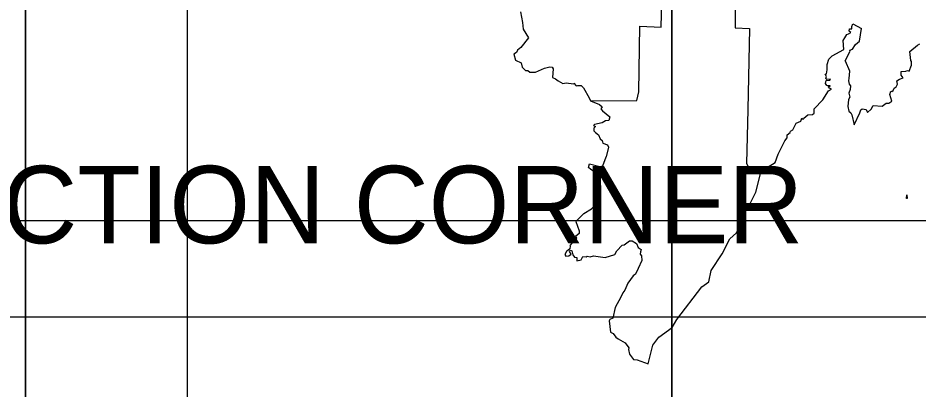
# Model space of a CAD drawing. Extents: x 2146475 to 2147951, y 2147003 to 2148003.
# Drawn here: x 2147652.9 to 2147708.6, y 2147812.5 to 2147835.5 of the extents above; entities that cross this region are included whole.
import ezdxf

# ---------------------------------------------------------------- set-up
doc = ezdxf.new("R2010")
doc.units = 0
for name, color, linetype in [('Sheet_Border_Prof3_Grid+Sta+EL_04_040+08_080', 7, 'Continuous'), ('Sheet_Border_Prof3_Grid+Sta+EL_10_100+20_200', 7, 'Continuous'), ('Sheet_Border_TitleSheet', 7, 'Continuous'), ('Sheet_Border_XS_Grid', 7, 'Continuous'), ('Sheet_Label_Misc_Wt1', 7, 'Continuous')]:
    doc.layers.add(name, color=color, linetype=linetype)

msp = doc.modelspace()

# ---------------------------------------------------------------- linework, layer by layer
at = {"layer": 'Sheet_Border_Prof3_Grid+Sta+EL_04_040+08_080'}
msp.add_line((2147663.414, 2147910.951), (2147663.414, 2147136.951), dxfattribs=at)
at = {"layer": 'Sheet_Border_Prof3_Grid+Sta+EL_10_100+20_200'}
for p, q in [((2147653.414, 2147896.951), (2147653.414, 2147152.951)), ((2147693.414, 2147896.951), (2147693.414, 2147152.951)), ((2147813.414, 2147816.951), (2146613.414, 2147816.951))]:
    msp.add_line(p, q, dxfattribs=at)
at = {"layer": 'Sheet_Border_TitleSheet'}
for points in [[(2147691.379, 2147830.925), (2147691.437, 2147834.989), (2147692.762, 2147834.927), (2147692.813, 2147837.395)], [(2147697.355, 2147837.179), (2147697.33, 2147834.879), (2147698.213, 2147834.845), (2147698.11, 2147829.821)], [(2147684.047, 2147835.863), (2147684.162, 2147835.217), (2147684.22, 2147834.797), (2147684.55, 2147834.253)], [(2147704.054, 2147833.539), (2147704.026, 2147834.097), (2147704.12, 2147834.269), (2147704.249, 2147834.465), (2147704.355, 2147834.513), (2147704.489, 2147834.597), (2147704.382, 2147834.667), (2147704.419, 2147834.823), (2147704.56, 2147834.811), (2147704.547, 2147834.955), (2147704.62, 2147835.121), (2147705.162, 2147834.839)], [(2147704.142, 2147832.835), (2147704.457, 2147833.431), (2147704.434, 2147833.495), (2147704.585, 2147833.565), (2147704.782, 2147833.849), (2147705.02, 2147834.053), (2147705.162, 2147834.839)], [(2147684.55, 2147834.253), (2147684.069, 2147833.663), (2147683.861, 2147833.497), (2147683.809, 2147833.351), (2147683.64, 2147833.241), (2147683.729, 2147832.887), (2147684.096, 2147832.721), (2147684.158, 2147832.435), (2147684.365, 2147832.239), (2147684.495, 2147832.247), (2147684.618, 2147832.143), (2147684.978, 2147832.125), (2147685.54, 2147832.381)], [(2147708.134, 2147833.425), (2147708.609, 2147833.817), (2147708.762, 2147833.881)], [(2147702.766, 2147830.419), (2147703.11, 2147830.981), (2147703.3, 2147831.085), (2147703.164, 2147831.145), (2147703.093, 2147831.259), (2147703.221, 2147831.261), (2147703.209, 2147831.291), (2147703.003, 2147831.319), (2147702.93, 2147831.429), (2147702.972, 2147831.621), (2147703.192, 2147831.645), (2147703.227, 2147831.705), (2147703.016, 2147831.679), (2147702.951, 2147831.751), (2147702.99, 2147831.859), (2147702.911, 2147832.009), (2147702.986, 2147832.041), (2147703.033, 2147832.281), (2147703.02, 2147832.617), (2147703.132, 2147832.935), (2147703.34, 2147833.155), (2147704.054, 2147833.539)], [(2147704.693, 2147828.883), (2147705.041, 2147829.621), (2147705.103, 2147829.811), (2147705.191, 2147829.863), (2147705.443, 2147829.813), (2147705.53, 2147829.647), (2147705.742, 2147829.835), (2147705.88, 2147830.079), (2147706.439, 2147830.019), (2147706.679, 2147830.205), (2147706.85, 2147830.211), (2147707.022, 2147830.347), (2147706.899, 2147830.749), (2147706.966, 2147830.959), (2147707.023, 2147830.937), (2147707.107, 2147830.995), (2147707.177, 2147831.135), (2147707.303, 2147831.219), (2147707.382, 2147831.399), (2147707.333, 2147831.603), (2147707.505, 2147831.703), (2147707.731, 2147831.779), (2147707.61, 2147831.943), (2147707.608, 2147832.173), (2147707.898, 2147832.195), (2147708.005, 2147832.247), (2147708.097, 2147832.203), (2147708.247, 2147832.577), (2147708.252, 2147832.795), (2147708.2, 2147832.855), (2147708.134, 2147833.425)], [(2147704.142, 2147832.835), (2147704.412, 2147832.215), (2147704.393, 2147831.941), (2147704.364, 2147831.765), (2147704.356, 2147831.595), (2147704.393, 2147831.399), (2147704.461, 2147831.283), (2147704.452, 2147831.061), (2147704.376, 2147830.825), (2147704.429, 2147830.585), (2147704.35, 2147830.439), (2147704.299, 2147830.015), (2147704.363, 2147829.709), (2147704.498, 2147829.615), (2147704.561, 2147829.487), (2147704.693, 2147828.883)], [(2147685.54, 2147832.381), (2147685.865, 2147832.469), (2147686.001, 2147832.453), (2147686.06, 2147832.343)], [(2147686.06, 2147832.343), (2147686.033, 2147831.799), (2147686.222, 2147831.713), (2147686.378, 2147831.589), (2147686.667, 2147831.431), (2147686.868, 2147831.477), (2147687.327, 2147831.415), (2147687.347, 2147831.455), (2147687.482, 2147831.295), (2147687.567, 2147831.307), (2147687.81, 2147831.307), (2147687.95, 2147831.171), (2147688.306, 2147830.545)], [(2147688.384, 2147830.357), (2147691.256, 2147830.383), (2147691.379, 2147830.925)], [(2147688.306, 2147830.545), (2147688.384, 2147830.357)], [(2147688.384, 2147830.357), (2147688.943, 2147830.133), (2147689.107, 2147829.983), (2147689.024, 2147829.857), (2147689.112, 2147829.737), (2147689.358, 2147829.563), (2147689.574, 2147829.377), (2147689.506, 2147829.139), (2147689.298, 2147829.115), (2147689.096, 2147829.001), (2147688.618, 2147828.891), (2147688.573, 2147828.841), (2147688.688, 2147828.779), (2147688.588, 2147828.657), (2147688.586, 2147828.505), (2147688.697, 2147828.389), (2147688.876, 2147828.243), (2147688.978, 2147827.999), (2147689.095, 2147827.907), (2147689.149, 2147827.747), (2147689.44, 2147827.631), (2147689.491, 2147827.499), (2147689.358, 2147826.889)], [(2147698.963, 2147825.917), (2147699.384, 2147826.279), (2147699.804, 2147826.541), (2147699.993, 2147827.057), (2147700.406, 2147827.891), (2147700.549, 2147828.069), (2147700.554, 2147828.255), (2147700.734, 2147828.397), (2147700.767, 2147828.483), (2147700.903, 2147828.557), (2147701.117, 2147828.977), (2147701.39, 2147829.099), (2147701.46, 2147829.279), (2147701.543, 2147829.199), (2147701.579, 2147829.277), (2147701.823, 2147829.491), (2147702.124, 2147829.521), (2147702.217, 2147829.597), (2147702.232, 2147829.865), (2147702.766, 2147830.419)], [(2147698.11, 2147829.821), (2147698.042, 2147826.471), (2147698.338, 2147825.929)], [(2147687.474, 2147822.875), (2147687.974, 2147823.373), (2147688.437, 2147823.679), (2147688.666, 2147823.923), (2147688.648, 2147824.055), (2147688.733, 2147824.137), (2147688.99, 2147824.655), (2147688.793, 2147825.009), (2147688.785, 2147825.753), (2147688.563, 2147825.995), (2147688.39, 2147826.097), (2147688.262, 2147826.233), (2147688.324, 2147826.461), (2147688.953, 2147826.301), (2147689.14, 2147826.339), (2147689.358, 2147826.889)], [(2147691.945, 2147814.065), (2147692.24, 2147815.229), (2147692.618, 2147815.727), (2147693.43, 2147816.323), (2147693.718, 2147816.811), (2147695.279, 2147818.833), (2147695.704, 2147819.155), (2147695.837, 2147819.847), (2147696.533, 2147820.875), (2147697.001, 2147821.805), (2147697.406, 2147822.189), (2147697.801, 2147822.779), (2147697.644, 2147823.127), (2147697.784, 2147823.433), (2147698.205, 2147823.881), (2147698.617, 2147824.693), (2147698.913, 2147825.917)], [(2147698.338, 2147825.929), (2147698.913, 2147825.917)], [(2147698.913, 2147825.917), (2147698.963, 2147825.917)], [(2147707.972, 2147824.303), (2147707.945, 2147824.307), (2147707.965, 2147824.535), (2147707.972, 2147824.303)], [(2147687.474, 2147822.875), (2147687.67, 2147822.305), (2147687.685, 2147822.133), (2147687.46, 2147821.953), (2147687.504, 2147821.849), (2147687.412, 2147821.669), (2147687.254, 2147821.567), (2147687.1, 2147821.403), (2147687.125, 2147821.361), (2147687.091, 2147821.201), (2147686.903, 2147821.033), (2147686.793, 2147820.841), (2147686.851, 2147820.737), (2147687.036, 2147820.759), (2147687.182, 2147820.869), (2147687.074, 2147821.035), (2147687.144, 2147821.113), (2147687.219, 2147821.067), (2147687.276, 2147820.819), (2147687.391, 2147820.683), (2147687.527, 2147820.653), (2147687.539, 2147820.439), (2147687.798, 2147820.519), (2147687.913, 2147820.715), (2147688.118, 2147820.687), (2147688.178, 2147820.745), (2147688.363, 2147820.693), (2147688.56, 2147820.753), (2147689.29, 2147820.649)], [(2147689.29, 2147820.649), (2147689.884, 2147820.845), (2147690.019, 2147821.071), (2147690.343, 2147821.413), (2147690.465, 2147821.445), (2147690.796, 2147821.697), (2147690.952, 2147821.691), (2147691.223, 2147821.523), (2147691.335, 2147821.265), (2147691.511, 2147821.157), (2147691.482, 2147821.007), (2147691.447, 2147820.851), (2147691.529, 2147820.755), (2147691.553, 2147820.465), (2147691.331, 2147819.979), (2147691.171, 2147819.617), (2147691.017, 2147819.511), (2147690.686, 2147819.073), (2147690.503, 2147818.625), (2147690.372, 2147818.469), (2147690.247, 2147818.197), (2147689.912, 2147817.547)], [(2147689.912, 2147817.547), (2147689.761, 2147816.901), (2147689.568, 2147816.813), (2147689.541, 2147816.721), (2147689.618, 2147816.037), (2147689.791, 2147815.953), (2147689.945, 2147815.711), (2147690.099, 2147815.613), (2147690.534, 2147815.373), (2147690.747, 2147815.065), (2147690.722, 2147814.963), (2147690.803, 2147814.675), (2147691.048, 2147814.345), (2147691.267, 2147814.307), (2147691.945, 2147814.065)]]:
    msp.add_lwpolyline(points, dxfattribs=at)
msp.add_circle((2147721.414, 2147804.998), 95.071, dxfattribs=at)
at = {"layer": 'Sheet_Border_XS_Grid'}
for p, q in [((2147653.414, 2147142.951), (2147653.414, 2147902.951)), ((2147693.414, 2147142.951), (2147693.414, 2147902.951)), ((2146573.414, 2147822.951), (2147853.414, 2147822.951))]:
    msp.add_line(p, q, dxfattribs=at)

# ---------------------------------------------------------------- texts
at = {"layer": 'Sheet_Label_Misc_Wt1'}
msp.add_text('SECTION CORNER', height=4.8, dxfattribs=at).set_placement((2147643.414, 2147821.532))

doc.saveas('drawing.dxf')
